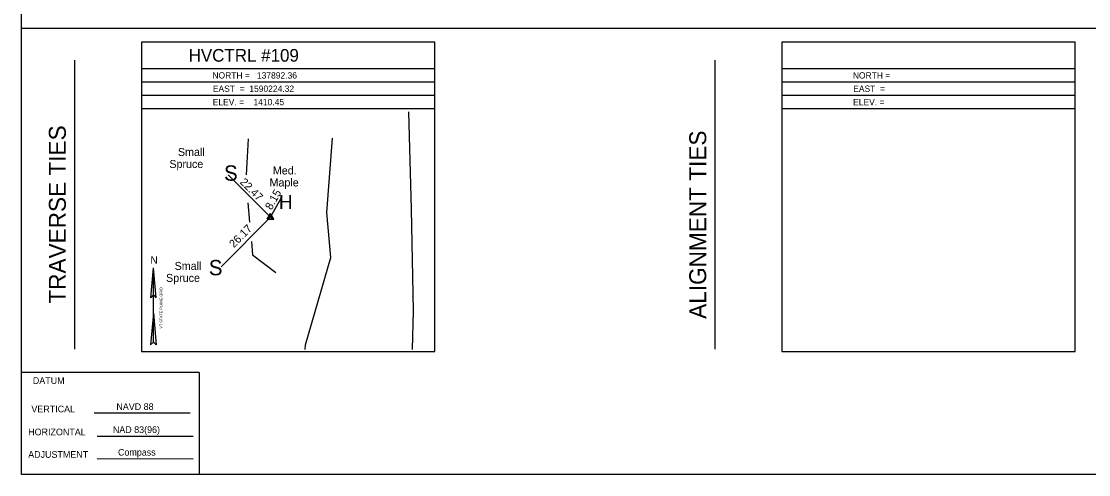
# Model space of a CAD drawing. Extents: x 1589528 to 1590208, y 135765 to 136632.
# Drawn here: x 1589528.2 to 1589928.2, y 135765.3 to 135935.2 of the extents above; entities that cross this region are included whole.
import ezdxf

# ---------------------------------------------------------------- set-up
doc = ezdxf.new("R2010")
doc.units = 0
for name, color, linetype in [('CPSM', 7, 'Continuous'), ('Default', 7, 'Continuous'), ('LARO', 7, 'Continuous'), ('Level 1', 7, 'Continuous'), ('Level 14', 7, 'Continuous'), ('Level 2', 7, 'Continuous'), ('LWS', 7, 'Continuous'), ('NBL1', 7, 'Continuous')]:
    doc.layers.add(name, color=color, linetype=linetype)

msp = doc.modelspace()

# ---------------------------------------------------------------- linework, layer by layer
at = {"layer": 'CPSM'}
for p, q in [((1589620.37, 135861.01), (1589621.62, 135863.18)), ((1589620.37, 135861.01), (1589621.62, 135861.74)), ((1589620.37, 135861.01), (1589622.87, 135861.01)), ((1589622.87, 135861.01), (1589621.62, 135863.18)), ((1589621.62, 135861.74), (1589621.62, 135863.18)), ((1589621.62, 135861.74), (1589621.62, 135861.74)), ((1589621.62, 135861.74), (1589622.87, 135861.01))]:
    msp.add_line(p, q, dxfattribs=at)
at = {"layer": 'Default'}
for q in [(1589605.74, 135877.62), (1589625.62, 135868.89), (1589603.12, 135843.23)]:
    msp.add_line((1589621.62, 135861.74), q, dxfattribs=at)
at = {"layer": 'LARO'}
for points in [[(1589613.22, 135891.15), (1589612.51, 135877.63)], [(1589634.61, 135812.26), (1589634.78, 135813.9), (1589644.22, 135846.7), (1589642.69, 135863.56), (1589644.85, 135891.39)], [(1589613.05, 135867.14), (1589613.74, 135859.88)], [(1589614.42, 135852.67), (1589614.89, 135847.66), (1589623.58, 135841.08)]]:
    msp.add_lwpolyline(points, dxfattribs=at)
at = {"layer": 'Level 1'}
for p, q in [((1589576.71, 135831.61), (1589577.71, 135842.85)), ((1589577.71, 135814.91), (1589577.71, 135842.85)), ((1589578.71, 135831.61), (1589577.71, 135842.85)), ((1589576.71, 135831.61), (1589577.71, 135832.71)), ((1589578.71, 135831.61), (1589577.71, 135832.71)), ((1589577.71, 135825.76), (1589576.67, 135813.99)), ((1589577.71, 135825.76), (1589578.75, 135813.99)), ((1589577.71, 135814.91), (1589576.67, 135813.99)), ((1589577.71, 135814.91), (1589578.75, 135813.99))]:
    msp.add_line(p, q, dxfattribs=at)
at = {"layer": 'LWS'}
msp.add_lwpolyline([(1589673.36, 135901.32), (1589674.35, 135864.74), (1589675.11, 135826.74), (1589674.68, 135812.26)], dxfattribs=at)
at = {"layer": 'NBL1'}
for p, q in [((1589528.23, 135932.62), (1590208.23, 135932.62)), ((1589548.23, 135812.29), (1589548.23, 135920.62)), ((1589788.23, 135812.29), (1589788.23, 135920.62)), ((1589683.23, 135917.45), (1589573.23, 135917.45)), ((1589923.23, 135917.45), (1589813.23, 135917.45)), ((1589683.23, 135912.45), (1589573.23, 135912.45)), ((1589923.23, 135912.45), (1589813.23, 135912.45)), ((1589683.23, 135907.45), (1589573.23, 135907.45)), ((1589923.23, 135907.45), (1589813.23, 135907.45)), ((1589683.23, 135902.45), (1589573.23, 135902.45)), ((1589923.23, 135902.45), (1589813.23, 135902.45)), ((1589594.89, 135803.54), (1589528.23, 135803.54)), ((1589594.89, 135803.54), (1589594.89, 135765.29)), ((1589594.89, 135803.54), (1589594.89, 135765.29)), ((1589555.47, 135788.52), (1589591.47, 135788.48)), ((1589556.58, 135779.74), (1589592.58, 135779.74)), ((1589556.58, 135771.31), (1589592.58, 135771.27))]:
    msp.add_line(p, q, dxfattribs=at)
for points in [[(1590208.23, 135765.29), (1589528.23, 135765.29), (1589528.23, 136185.29), (1590208.23, 136185.29)], [(1589573.23, 135811.45), (1589683.23, 135811.45), (1589683.23, 135927.45), (1589573.23, 135927.45)], [(1589813.23, 135811.45), (1589923.23, 135811.45), (1589923.23, 135927.45), (1589813.23, 135927.45)]]:
    msp.add_lwpolyline(points, close=True, dxfattribs=at)

# ---------------------------------------------------------------- texts
at = {"layer": 'Default'}
for s, rotation, p in [('22.47', 315, (1589609.92, 135874.69)), ('8.15', 60.7844, (1589621.97, 135864.28)), ('26.17', 45, (1589607.89, 135850.12))]:
    msp.add_text(s, height=3, rotation=rotation, dxfattribs=at).set_placement(p)
at = {"layer": 'Level 1'}
msp.add_text('N', height=2.85, dxfattribs=at).set_placement((1589576.6, 135844.31))
msp.add_text('VT STATE PLANE GRID', height=1.0092, rotation=90.0204, dxfattribs=at).set_placement((1589581.1, 135820.05))
at = {"layer": 'Level 14'}
for s, height, p in [('S', 5.75, (1589604.19, 135875.46)), ('H', 5.3, (1589624.74, 135864.85)), ('S', 5.75, (1589598.48, 135840.01))]:
    msp.add_text(s, height=height, dxfattribs=at).set_placement(p)
at = {"layer": 'Level 2'}
for s, p in [('Small', (1589586.91, 135884.74)), ('Spruce', (1589583.7, 135880.24)), ('Med.', (1589622.48, 135877.81)), ('Maple', (1589621.25, 135873.31)), ('Small', (1589585.67, 135842.03)), ('Spruce', (1589582.46, 135837.53))]:
    msp.add_text(s, height=3, dxfattribs=at).set_placement(p)
at = {"layer": 'NBL1'}
for s, height, p in [('    HVCTRL #109    ', 4.75, (1589583.87, 135920.08)), ('NORTH =   137892.36 ', 2.375, (1589599.84, 135913.76)), ('NORTH =             ', 2.375, (1589839.84, 135913.76)), ('EAST  =  1590224.32 ', 2.375, (1589599.99, 135908.76)), ('EAST  =             ', 2.375, (1589839.99, 135908.76)), ('ELEV. =    1410.45  ', 2.375, (1589599.95, 135903.76)), ('ELEV. =             ', 2.375, (1589839.95, 135903.76)), ('DATUM', 2.5, (1589532.54, 135799.3)), ('  NAVD 88 ', 2.5, (1589561.99, 135789.53)), ('HORIZONTAL', 2.5, (1589530.8, 135780.04)), ('NAD 83(96) ', 2.5, (1589562.53, 135780.91)), ('ADJUSTMENT', 2.5, (1589530.8, 135771.6)), ('  Compass ', 2.5, (1589562.59, 135772.43))]:
    msp.add_text(s, height=height, dxfattribs=at).set_placement(p)
for s, height, rotation, p in [('TRAVERSE TIES', 6.3332, 90, (1589544.89, 135829.39)), ('ALIGNMENT TIES', 6.3332, 90, (1589784.89, 135823.69)), ('VERTICAL', 2.5, 0.1439, (1589532, 135788.63))]:
    msp.add_text(s, height=height, rotation=rotation, dxfattribs=at).set_placement(p)

doc.saveas('drawing.dxf')
